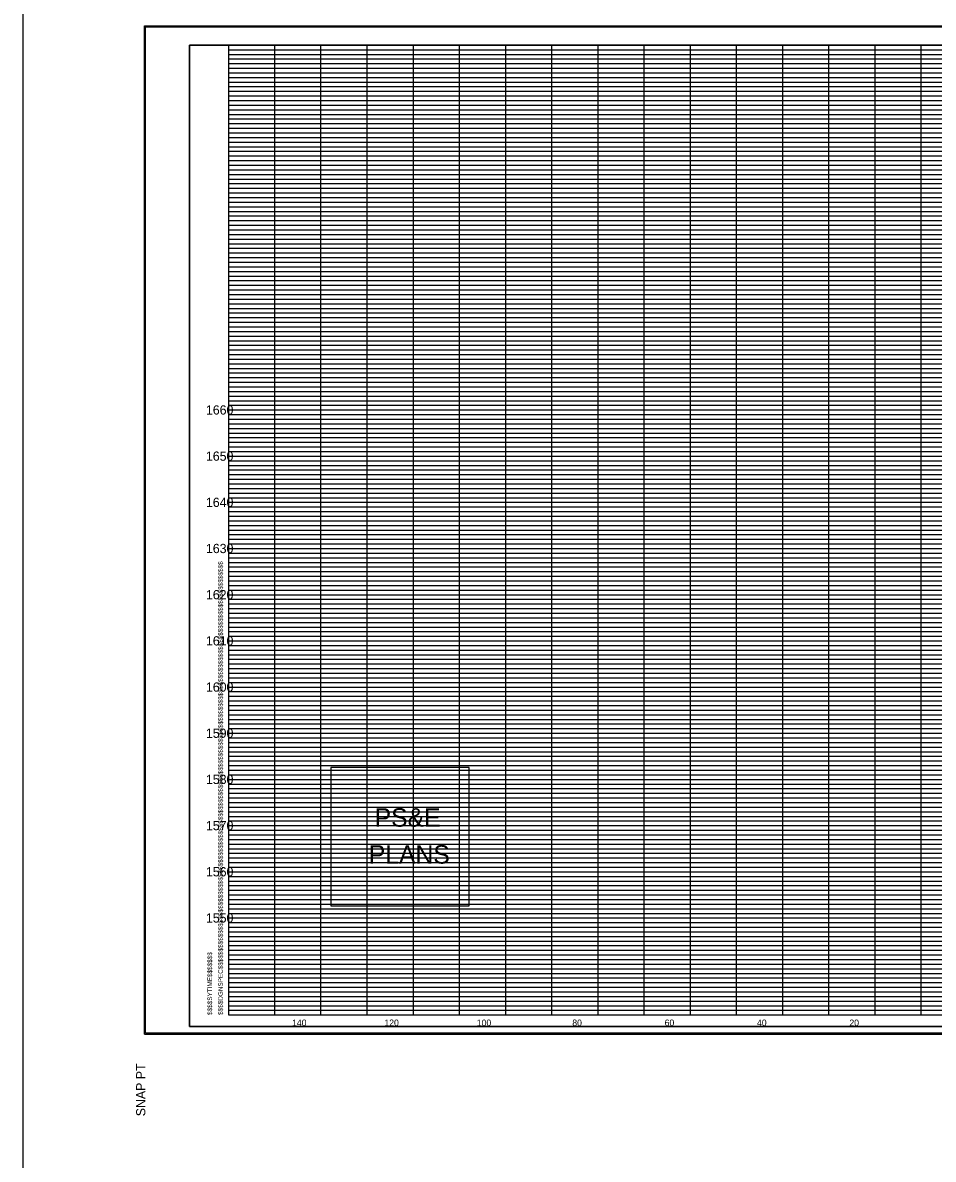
# Model space of a CAD drawing. Extents: x 955 to 1375, y 1248 to 3657.
# Drawn here: x 955.4 to 1152.6, y 2858.7 to 3104.8 of the extents above; entities that cross this region are included whole.
import ezdxf

# ---------------------------------------------------------------- set-up
doc = ezdxf.new("R2010")
doc.units = 0
for name, color, linetype in [('DESIGN - SHEET - Corner Text', 7, 'Continuous'), ('DESIGN - SHEET - Light Grid', 7, 'Continuous'), ('DESIGN - SHEET - Linework', 7, 'Continuous'), ('DESIGN - SHEET - Plot Shape', 7, 'Continuous'), ('DESIGN - TYPICAL - Text', 7, 'Continuous'), ('DESIGN - UTILITIES - Cable (Overhead) with Text', 7, 'Continuous'), ('SURVEY - NON-TRANSPORTATION - Features Text', 7, 'Continuous')]:
    doc.layers.add(name, color=color, linetype=linetype)

# ---------------------------------------------------------------- blocks, each defined once
blk = doc.blocks.new('XSTSHT')
at = {"layer": 'DESIGN - SHEET - Light Grid'}
for p, q in [((0, 20.9), (8, 20.9)), ((0, 20.8), (8, 20.8)), ((0, 20.7), (8, 20.7)), ((8, 20.9), (16, 20.9)), ((8, 20.8), (16, 20.8)), ((8, 20.7), (16, 20.7)), ((0, 20.6), (8, 20.6)), ((0, 20.5), (8, 20.5)), ((8, 20.6), (16, 20.6)), ((8, 20.5), (16, 20.5)), ((0, 20.4), (8, 20.4)), ((0, 20.3), (8, 20.3)), ((0, 20.2), (8, 20.2)), ((8, 20.4), (16, 20.4)), ((8, 20.3), (16, 20.3)), ((8, 20.2), (16, 20.2)), ((0, 20.1), (8, 20.1)), ((8, 20.1), (16, 20.1)), ((0, 19.9), (8, 19.9)), ((0, 19.8), (8, 19.8)), ((0, 19.7), (8, 19.7)), ((8, 19.9), (16, 19.9)), ((8, 19.8), (16, 19.8)), ((8, 19.7), (16, 19.7)), ((0, 19.6), (8, 19.6)), ((0, 19.5), (8, 19.5)), ((8, 19.6), (16, 19.6)), ((8, 19.5), (16, 19.5)), ((0, 19.4), (8, 19.4)), ((0, 19.3), (8, 19.3)), ((0, 19.2), (8, 19.2)), ((8, 19.4), (16, 19.4)), ((8, 19.3), (16, 19.3)), ((8, 19.2), (16, 19.2)), ((0, 19.1), (8, 19.1)), ((8, 19.1), (16, 19.1)), ((0, 18.9), (8, 18.9)), ((0, 18.8), (8, 18.8)), ((8, 18.9), (16, 18.9)), ((8, 18.8), (16, 18.8)), ((0, 18.7), (8, 18.7)), ((0, 18.6), (8, 18.6)), ((0, 18.5), (8, 18.5)), ((8, 18.7), (16, 18.7)), ((8, 18.6), (16, 18.6)), ((8, 18.5), (16, 18.5)), ((0, 18.4), (8, 18.4)), ((0, 18.3), (8, 18.3)), ((8, 18.4), (16, 18.4)), ((8, 18.3), (16, 18.3)), ((0, 18.2), (8, 18.2)), ((0, 18.1), (8, 18.1)), ((8, 18.2), (16, 18.2)), ((8, 18.1), (16, 18.1)), ((0, 17.9), (8, 17.9)), ((0, 17.8), (8, 17.8)), ((8, 17.9), (16, 17.9)), ((8, 17.8), (16, 17.8)), ((0, 17.7), (8, 17.7)), ((0, 17.6), (8, 17.6)), ((0, 17.5), (8, 17.5)), ((8, 17.7), (16, 17.7)), ((8, 17.6), (16, 17.6)), ((8, 17.5), (16, 17.5)), ((0, 17.4), (8, 17.4)), ((0, 17.3), (8, 17.3)), ((8, 17.4), (16, 17.4)), ((8, 17.3), (16, 17.3)), ((0, 17.2), (8, 17.2)), ((0, 17.1), (8, 17.1)), ((8, 17.2), (16, 17.2)), ((8, 17.1), (16, 17.1)), ((0, 16.9), (8, 16.9)), ((0, 16.8), (8, 16.8)), ((8, 16.9), (16, 16.9)), ((8, 16.8), (16, 16.8)), ((0, 16.7), (8, 16.7)), ((0, 16.6), (8, 16.6)), ((0, 16.5), (8, 16.5)), ((8, 16.7), (16, 16.7)), ((8, 16.6), (16, 16.6)), ((8, 16.5), (16, 16.5)), ((0, 16.4), (8, 16.4)), ((0, 16.3), (8, 16.3)), ((8, 16.4), (16, 16.4)), ((8, 16.3), (16, 16.3)), ((0, 16.2), (8, 16.2)), ((0, 16.1), (8, 16.1)), ((8, 16.2), (16, 16.2)), ((8, 16.1), (16, 16.1)), ((0, 15.9), (8, 15.9)), ((0, 15.8), (8, 15.8)), ((8, 15.9), (16, 15.9)), ((8, 15.8), (16, 15.8)), ((0, 15.7), (8, 15.7)), ((0, 15.6), (8, 15.6)), ((8, 15.7), (16, 15.7)), ((8, 15.6), (16, 15.6)), ((0, 15.5), (8, 15.5)), ((0, 15.4), (8, 15.4)), ((0, 15.3), (8, 15.3)), ((8, 15.5), (16, 15.5)), ((8, 15.4), (16, 15.4)), ((8, 15.3), (16, 15.3)), ((0, 15.2), (8, 15.2)), ((0, 15.1), (8, 15.1)), ((8, 15.2), (16, 15.2)), ((8, 15.1), (16, 15.1)), ((0, 14.9), (8, 14.9)), ((0, 14.8), (8, 14.8)), ((8, 14.9), (16, 14.9)), ((8, 14.8), (16, 14.8)), ((0, 14.7), (8, 14.7)), ((0, 14.6), (8, 14.6)), ((8, 14.7), (16, 14.7)), ((8, 14.6), (16, 14.6)), ((0, 14.5), (8, 14.5)), ((0, 14.4), (8, 14.4)), ((0, 14.3), (8, 14.3)), ((8, 14.5), (16, 14.5)), ((8, 14.4), (16, 14.4)), ((8, 14.3), (16, 14.3)), ((0, 14.2), (8, 14.2)), ((0, 14.1), (8, 14.1)), ((8, 14.2), (16, 14.2)), ((8, 14.1), (16, 14.1)), ((0, 13.9), (8, 13.9)), ((0, 13.8), (8, 13.8)), ((8, 13.9), (16, 13.9)), ((8, 13.8), (16, 13.8)), ((0, 13.7), (8, 13.7)), ((0, 13.6), (8, 13.6)), ((8, 13.7), (16, 13.7)), ((8, 13.6), (16, 13.6)), ((0, 13.5), (8, 13.5)), ((0, 13.4), (8, 13.4)), ((0, 13.3), (8, 13.3)), ((8, 13.5), (16, 13.5)), ((8, 13.4), (16, 13.4)), ((8, 13.3), (16, 13.3)), ((0, 13.2), (8, 13.2)), ((0, 13.1), (8, 13.1)), ((8, 13.2), (16, 13.2)), ((8, 13.1), (16, 13.1)), ((0, 12.9), (8, 12.9)), ((0, 12.8), (8, 12.8)), ((8, 12.9), (16, 12.9)), ((8, 12.8), (16, 12.8)), ((0, 12.7), (8, 12.7)), ((0, 12.6), (8, 12.6)), ((8, 12.7), (16, 12.7)), ((8, 12.6), (16, 12.6)), ((0, 12.5), (8, 12.5)), ((0, 12.4), (8, 12.4)), ((8, 12.5), (16, 12.5)), ((8, 12.4), (16, 12.4)), ((0, 12.3), (8, 12.3)), ((0, 12.2), (8, 12.2)), ((0, 12.1), (8, 12.1)), ((8, 12.3), (16, 12.3)), ((8, 12.2), (16, 12.2)), ((8, 12.1), (16, 12.1)), ((0, 11.9), (8, 11.9)), ((8, 11.9), (16, 11.9)), ((0, 11.8), (8, 11.8)), ((0, 11.7), (8, 11.7)), ((0, 11.6), (8, 11.6)), ((8, 11.8), (16, 11.8)), ((8, 11.7), (16, 11.7)), ((8, 11.6), (16, 11.6)), ((0, 11.5), (8, 11.5)), ((0, 11.4), (8, 11.4)), ((8, 11.5), (16, 11.5)), ((8, 11.4), (16, 11.4)), ((0, 11.3), (8, 11.3)), ((0, 11.2), (8, 11.2)), ((0, 11.1), (8, 11.1)), ((8, 11.3), (16, 11.3)), ((8, 11.2), (16, 11.2)), ((8, 11.1), (16, 11.1)), ((0, 10.9), (8, 10.9)), ((8, 10.9), (16, 10.9)), ((0, 10.8), (8, 10.8)), ((0, 10.7), (8, 10.7)), ((0, 10.6), (8, 10.6)), ((8, 10.8), (16, 10.8)), ((8, 10.7), (16, 10.7)), ((8, 10.6), (16, 10.6)), ((0, 10.5), (8, 10.5)), ((0, 10.4), (8, 10.4)), ((8, 10.5), (16, 10.5)), ((8, 10.4), (16, 10.4)), ((0, 10.3), (8, 10.3)), ((0, 10.2), (8, 10.2)), ((0, 10.1), (8, 10.1)), ((8, 10.3), (16, 10.3)), ((8, 10.2), (16, 10.2)), ((8, 10.1), (16, 10.1)), ((0, 9.9), (8, 9.9)), ((8, 9.9), (16, 9.9)), ((0, 9.8), (8, 9.8)), ((0, 9.7), (8, 9.7)), ((0, 9.6), (8, 9.6)), ((8, 9.8), (16, 9.8)), ((8, 9.7), (16, 9.7)), ((8, 9.6), (16, 9.6)), ((0, 9.5), (8, 9.5)), ((0, 9.4), (8, 9.4)), ((8, 9.5), (16, 9.5)), ((8, 9.4), (16, 9.4)), ((0, 9.3), (8, 9.3)), ((0, 9.2), (8, 9.2)), ((8, 9.3), (16, 9.3)), ((8, 9.2), (16, 9.2)), ((0, 9.1), (8, 9.1)), ((0, 8.9), (8, 8.9)), ((8, 9.1), (16, 9.1)), ((8, 8.9), (16, 8.9)), ((0, 8.8), (8, 8.8)), ((0, 8.7), (8, 8.7)), ((8, 8.8), (16, 8.8)), ((8, 8.7), (16, 8.7)), ((0, 8.6), (8, 8.6)), ((0, 8.5), (8, 8.5)), ((0, 8.4), (8, 8.4)), ((8, 8.6), (16, 8.6)), ((8, 8.5), (16, 8.5)), ((8, 8.4), (16, 8.4)), ((0, 8.3), (8, 8.3)), ((0, 8.2), (8, 8.2)), ((8, 8.3), (16, 8.3)), ((8, 8.2), (16, 8.2)), ((0, 8.1), (8, 8.1)), ((0, 7.9), (8, 7.9)), ((8, 8.1), (16, 8.1)), ((8, 7.9), (16, 7.9)), ((0, 7.8), (8, 7.8)), ((0, 7.7), (8, 7.7)), ((8, 7.8), (16, 7.8)), ((8, 7.7), (16, 7.7)), ((0, 7.6), (8, 7.6)), ((0, 7.5), (8, 7.5)), ((0, 7.4), (8, 7.4)), ((8, 7.6), (16, 7.6)), ((8, 7.5), (16, 7.5)), ((8, 7.4), (16, 7.4)), ((0, 7.3), (8, 7.3)), ((0, 7.2), (8, 7.2)), ((8, 7.3), (16, 7.3)), ((8, 7.2), (16, 7.2)), ((0, 7.1), (8, 7.1)), ((0, 6.9), (8, 6.9)), ((8, 7.1), (16, 7.1)), ((8, 6.9), (16, 6.9)), ((0, 6.8), (8, 6.8)), ((0, 6.7), (8, 6.7)), ((8, 6.8), (16, 6.8)), ((8, 6.7), (16, 6.7)), ((0, 6.6), (8, 6.6)), ((0, 6.5), (8, 6.5)), ((0, 6.4), (8, 6.4)), ((8, 6.6), (16, 6.6)), ((8, 6.5), (16, 6.5)), ((8, 6.4), (16, 6.4)), ((0, 6.3), (8, 6.3)), ((0, 6.2), (8, 6.2)), ((8, 6.3), (16, 6.3)), ((8, 6.2), (16, 6.2)), ((0, 6.1), (8, 6.1)), ((8, 6.1), (16, 6.1)), ((0, 5.9), (8, 5.9)), ((0, 5.8), (8, 5.8)), ((0, 5.7), (8, 5.7)), ((8, 5.9), (16, 5.9)), ((8, 5.8), (16, 5.8)), ((8, 5.7), (16, 5.7)), ((0, 5.6), (8, 5.6)), ((0, 5.5), (8, 5.5)), ((8, 5.6), (16, 5.6)), ((8, 5.5), (16, 5.5)), ((0, 5.4), (8, 5.4)), ((0, 5.3), (8, 5.3)), ((0, 5.2), (8, 5.2)), ((8, 5.4), (16, 5.4)), ((8, 5.3), (16, 5.3)), ((8, 5.2), (16, 5.2)), ((0, 5.1), (8, 5.1)), ((8, 5.1), (16, 5.1)), ((0, 4.9), (8, 4.9)), ((0, 4.8), (8, 4.8)), ((0, 4.7), (8, 4.7)), ((8, 4.9), (16, 4.9)), ((8, 4.8), (16, 4.8)), ((8, 4.7), (16, 4.7)), ((0, 4.6), (8, 4.6)), ((0, 4.5), (8, 4.5)), ((8, 4.6), (16, 4.6)), ((8, 4.5), (16, 4.5)), ((0, 4.4), (8, 4.4)), ((0, 4.3), (8, 4.3)), ((0, 4.2), (8, 4.2)), ((8, 4.4), (16, 4.4)), ((8, 4.3), (16, 4.3)), ((8, 4.2), (16, 4.2)), ((0, 4.1), (8, 4.1)), ((8, 4.1), (16, 4.1)), ((0, 3.9), (8, 3.9)), ((0, 3.8), (8, 3.8)), ((0, 3.7), (8, 3.7)), ((8, 3.9), (16, 3.9)), ((8, 3.8), (16, 3.8)), ((8, 3.7), (16, 3.7)), ((0, 3.6), (8, 3.6)), ((0, 3.5), (8, 3.5)), ((8, 3.6), (16, 3.6)), ((8, 3.5), (16, 3.5)), ((0, 3.4), (8, 3.4)), ((0, 3.3), (8, 3.3)), ((0, 3.2), (8, 3.2)), ((8, 3.4), (16, 3.4)), ((8, 3.3), (16, 3.3)), ((8, 3.2), (16, 3.2)), ((0, 3.1), (8, 3.1)), ((8, 3.1), (16, 3.1)), ((0, 2.9), (8, 2.9)), ((0, 2.8), (8, 2.8)), ((8, 2.9), (16, 2.9)), ((8, 2.8), (16, 2.8)), ((0, 2.7), (8, 2.7)), ((0, 2.6), (8, 2.6)), ((0, 2.5), (8, 2.5)), ((8, 2.7), (16, 2.7)), ((8, 2.6), (16, 2.6)), ((8, 2.5), (16, 2.5)), ((0, 2.4), (8, 2.4)), ((0, 2.3), (8, 2.3)), ((8, 2.4), (16, 2.4)), ((8, 2.3), (16, 2.3)), ((0, 2.2), (8, 2.2)), ((0, 2.1), (8, 2.1)), ((8, 2.2), (16, 2.2)), ((8, 2.1), (16, 2.1)), ((0, 1.9), (8, 1.9)), ((0, 1.8), (8, 1.8)), ((8, 1.9), (16, 1.9)), ((8, 1.8), (16, 1.8)), ((0, 1.7), (8, 1.7)), ((0, 1.6), (8, 1.6)), ((0, 1.5), (8, 1.5)), ((8, 1.7), (16, 1.7)), ((8, 1.6), (16, 1.6)), ((8, 1.5), (16, 1.5)), ((0, 1.4), (8, 1.4)), ((0, 1.3), (8, 1.3)), ((8, 1.4), (16, 1.4)), ((8, 1.3), (16, 1.3)), ((0, 1.2), (8, 1.2)), ((0, 1.1), (8, 1.1)), ((8, 1.2), (16, 1.2)), ((8, 1.1), (16, 1.1)), ((0, 0.9), (8, 0.9)), ((0, 0.8), (8, 0.8)), ((8, 0.9), (16, 0.9)), ((8, 0.8), (16, 0.8)), ((0, 0.7), (8, 0.7)), ((0, 0.6), (8, 0.6)), ((0, 0.5), (8, 0.5)), ((8, 0.7), (16, 0.7)), ((8, 0.6), (16, 0.6)), ((8, 0.5), (16, 0.5)), ((0, 0.4), (8, 0.4)), ((0, 0.3), (8, 0.3)), ((8, 0.4), (16, 0.4)), ((8, 0.3), (16, 0.3)), ((0, 0.2), (8, 0.2)), ((0, 0.1), (8, 0.1)), ((8, 0.2), (16, 0.2)), ((8, 0.1), (16, 0.1))]:
    blk.add_line(p, q, dxfattribs=at)
at = {"layer": 'DESIGN - SHEET - Linework'}
for p, q in [((-1.823, -0.414), (-1.823, 21.414)), ((-1.823, 21.414), (32.217, 21.414)), ((1, 0), (1, 21)), ((2, 0), (2, 21)), ((3, 0), (3, 21)), ((4, 0), (4, 21)), ((5, 0), (5, 21)), ((6, 0), (6, 21)), ((7, 0), (7, 21)), ((8, 0), (8, 21)), ((9, 0), (9, 21)), ((10, 0), (10, 21)), ((11, 0), (11, 21)), ((12, 0), (12, 21)), ((13, 0), (13, 21)), ((14, 0), (14, 21)), ((15, 0), (15, 21)), ((0, 20), (28, 20)), ((0, 19), (32, 19)), ((0, 18), (32, 18)), ((0, 17), (32, 17)), ((0, 16), (32, 16)), ((0, 15), (32, 15)), ((0, 14), (32, 14)), ((0, 13), (32, 13)), ((0, 12), (32, 12)), ((0, 11), (32, 11)), ((0, 10), (32, 10)), ((0, 9), (32, 9)), ((0, 8), (32, 8)), ((0, 7), (32, 7)), ((0, 6), (32, 6)), ((0, 5), (32, 5)), ((0, 4), (32, 4)), ((0, 3), (32, 3)), ((0, 2), (32, 2)), ((0, 1), (32, 1)), ((-1.823, -0.414), (32.217, -0.414))]:
    blk.add_line(p, q, dxfattribs=at)
blk.add_lwpolyline([(0, 21), (0, 0), (32, 0), (32, 21), (0, 21)], dxfattribs=at)
at = {"layer": 'DESIGN - SHEET - Plot Shape'}
for points in [[(-1.803, 21.394), (32.197, 21.394), (32.197, -0.394), (-1.803, -0.394)], [(-0.85, 21), (32, 21), (32, -0.25), (-0.85, -0.25)]]:
    blk.add_lwpolyline(points, close=True, dxfattribs=at)
at = {"layer": 'DESIGN - SHEET - Corner Text'}
for s, height, p in [('$$$$DGNSPEC$$$$$$$$$$$$$$$$$$$$$$$$$$$$$$$$$$$$$$$$$$$$$$$$$$$$$$$$$$$$$$$$$$$$$$$$$$$$$$$$$$$$$$$$$$$$$$$$$$$$$$$$$$$$$$$$$$$', 0.100002, (-0.126, 0)), ('$$$$SYTIME$$$$$$$', 0.1, (-0.358, 0)), ('SNAP PT  ', 0.2, (-1.803, -2.194))]:
    blk.add_text(s, height=height, rotation=90, dxfattribs=at).set_placement(p)

msp = doc.modelspace()

# ---------------------------------------------------------------- linework, layer by layer
at = {"layer": 'DESIGN - SHEET - Corner Text'}
msp.add_lwpolyline([(1022.11, 2943.59), (1022.11, 2913.59), (1052.11, 2913.59), (1052.11, 2943.59)], close=True, dxfattribs=at)
at = {"layer": 'DESIGN - SHEET - Plot Shape'}
msp.add_lwpolyline([(991.5, 2887.5), (1320, 2887.5), (1320, 3100), (991.5, 3100)], close=True, dxfattribs=at)
at = {"layer": 'SURVEY - NON-TRANSPORTATION - Features Text'}
msp.add_lwpolyline([(955.41, 1505.76), (1344.98, 1505.76), (1344.98, 3398.01), (955.41, 3398.01)], close=True, dxfattribs=at)

# ---------------------------------------------------------------- block references
at = {"layer": 'DESIGN - UTILITIES - Cable (Overhead) with Text', "xscale": 10, "yscale": 10}
msp.add_blockref('XSTSHT', (1000, 2890), dxfattribs=at)

# ---------------------------------------------------------------- texts
at = {"layer": 'DESIGN - SHEET - Corner Text'}
for s, p in [('PS&E', (1031.63, 2930.76)), ('PLANS', (1030.35, 2922.76))]:
    msp.add_text(s, height=4, dxfattribs=at).set_placement(p)
at = {"layer": 'DESIGN - TYPICAL - Text'}
for s, height, p in [('     1660     ', 2, (991.37, 3020)), ('     1650     ', 2, (991.37, 3010)), ('     1640     ', 2, (991.37, 3000)), ('     1630     ', 2, (991.37, 2990)), ('     1620     ', 2, (991.37, 2980)), ('     1610     ', 2, (991.37, 2970)), ('     1600     ', 2, (991.37, 2960)), ('     1590     ', 2, (991.37, 2950)), ('     1580     ', 2, (991.37, 2940)), ('     1570     ', 2, (991.37, 2930)), ('     1560     ', 2, (991.37, 2920)), ('     1550     ', 2, (991.37, 2910)), ('     140     ', 1.4, (1011.14, 2887.6)), ('     120     ', 1.4, (1031.14, 2887.6)), ('     100     ', 1.4, (1051.14, 2887.6)), ('     80     ', 1.4, (1071.82, 2887.6)), ('     60     ', 1.4, (1091.82, 2887.6)), ('     40     ', 1.4, (1111.82, 2887.6)), ('     20     ', 1.4, (1131.82, 2887.6))]:
    msp.add_text(s, height=height, dxfattribs=at).set_placement(p)

doc.saveas('drawing.dxf')
